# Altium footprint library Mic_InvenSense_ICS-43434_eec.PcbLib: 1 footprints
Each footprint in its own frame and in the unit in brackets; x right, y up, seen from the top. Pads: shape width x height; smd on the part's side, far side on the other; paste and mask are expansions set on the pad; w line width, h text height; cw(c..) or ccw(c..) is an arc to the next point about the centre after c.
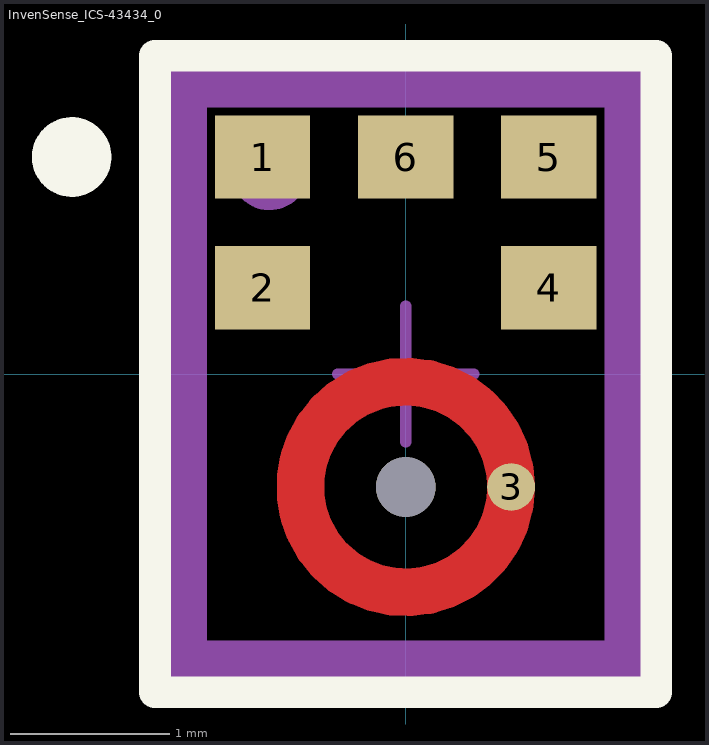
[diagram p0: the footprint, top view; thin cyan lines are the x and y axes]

## InvenSense_ICS-43434_0 [mm]
pads (12):
  rect 0.6x0.522 smd: 1(-0.9,1.364) 2(-0.9,0.542) 4(0.9,0.542) 5(0.9,1.364) 6(0,1.364)
  round 0.3 smd: 3(0.663,-0.71)
  rect 0.5x0.422 on Top Paste: ""(-0.9,0.542) ""(-0.9,1.364) ""(0,1.364) ""(0.9,0.542) ""(0.9,1.364)
  round 0.375 smd: ""(0,-0.71)
Top Layer:
  circle w0.3: c0,-0.71 r0.663
Top Overlay:
  circle w0.25: c-2.1,1.364 r0.125
  lines w0.2: -1.575,-2 -1.575,2 1.575,2 1.575,-2 -1.575,-2
Top Paste:
  lines w0.25: -0.665,-0.885 cw(c0,-0.71) -0.175,-1.375 ; -0.665,-0.535 ccw(c0,-0.71) -0.175,-0.045 ; 0.175,-1.375 cw(c0,-0.71) 0.665,-0.885 ; 0.175,-0.045 ccw(c0,-0.71) 0.665,-0.535
Top Solder:
  circle w0.3: c0,-0.71 r0.663
Mechanical 10:
  circle w0.25: c-0.855,1.28 r0.125
  lines w0.2: -1.425,-1.85 1.425,-1.85 1.425,1.85 -1.425,1.85 -1.425,-1.85
  text ".Designator" at 0,0 h1
Mechanical 12:
  lines w0.15: -1.325,-1.75 -1.325,1.75 1.325,1.75 1.325,-1.75 -1.325,-1.75
Mechanical 15:
  lines w0.07: -0.427,0 0.427,0 -0.427,0 ; 0,-0.427 0,0.427 0,-0.427
  lines w0.1: -1.425,-1.85 -1.425,1.85 1.425,1.85 1.425,-1.85 -1.425,-1.85
3D body "UNK_ICS-43434_eec.STEP": height 0.98, standoff 0, extent -1.325,-1.749 1.325,1.751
